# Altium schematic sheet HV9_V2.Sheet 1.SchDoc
size 431 x 279 mm
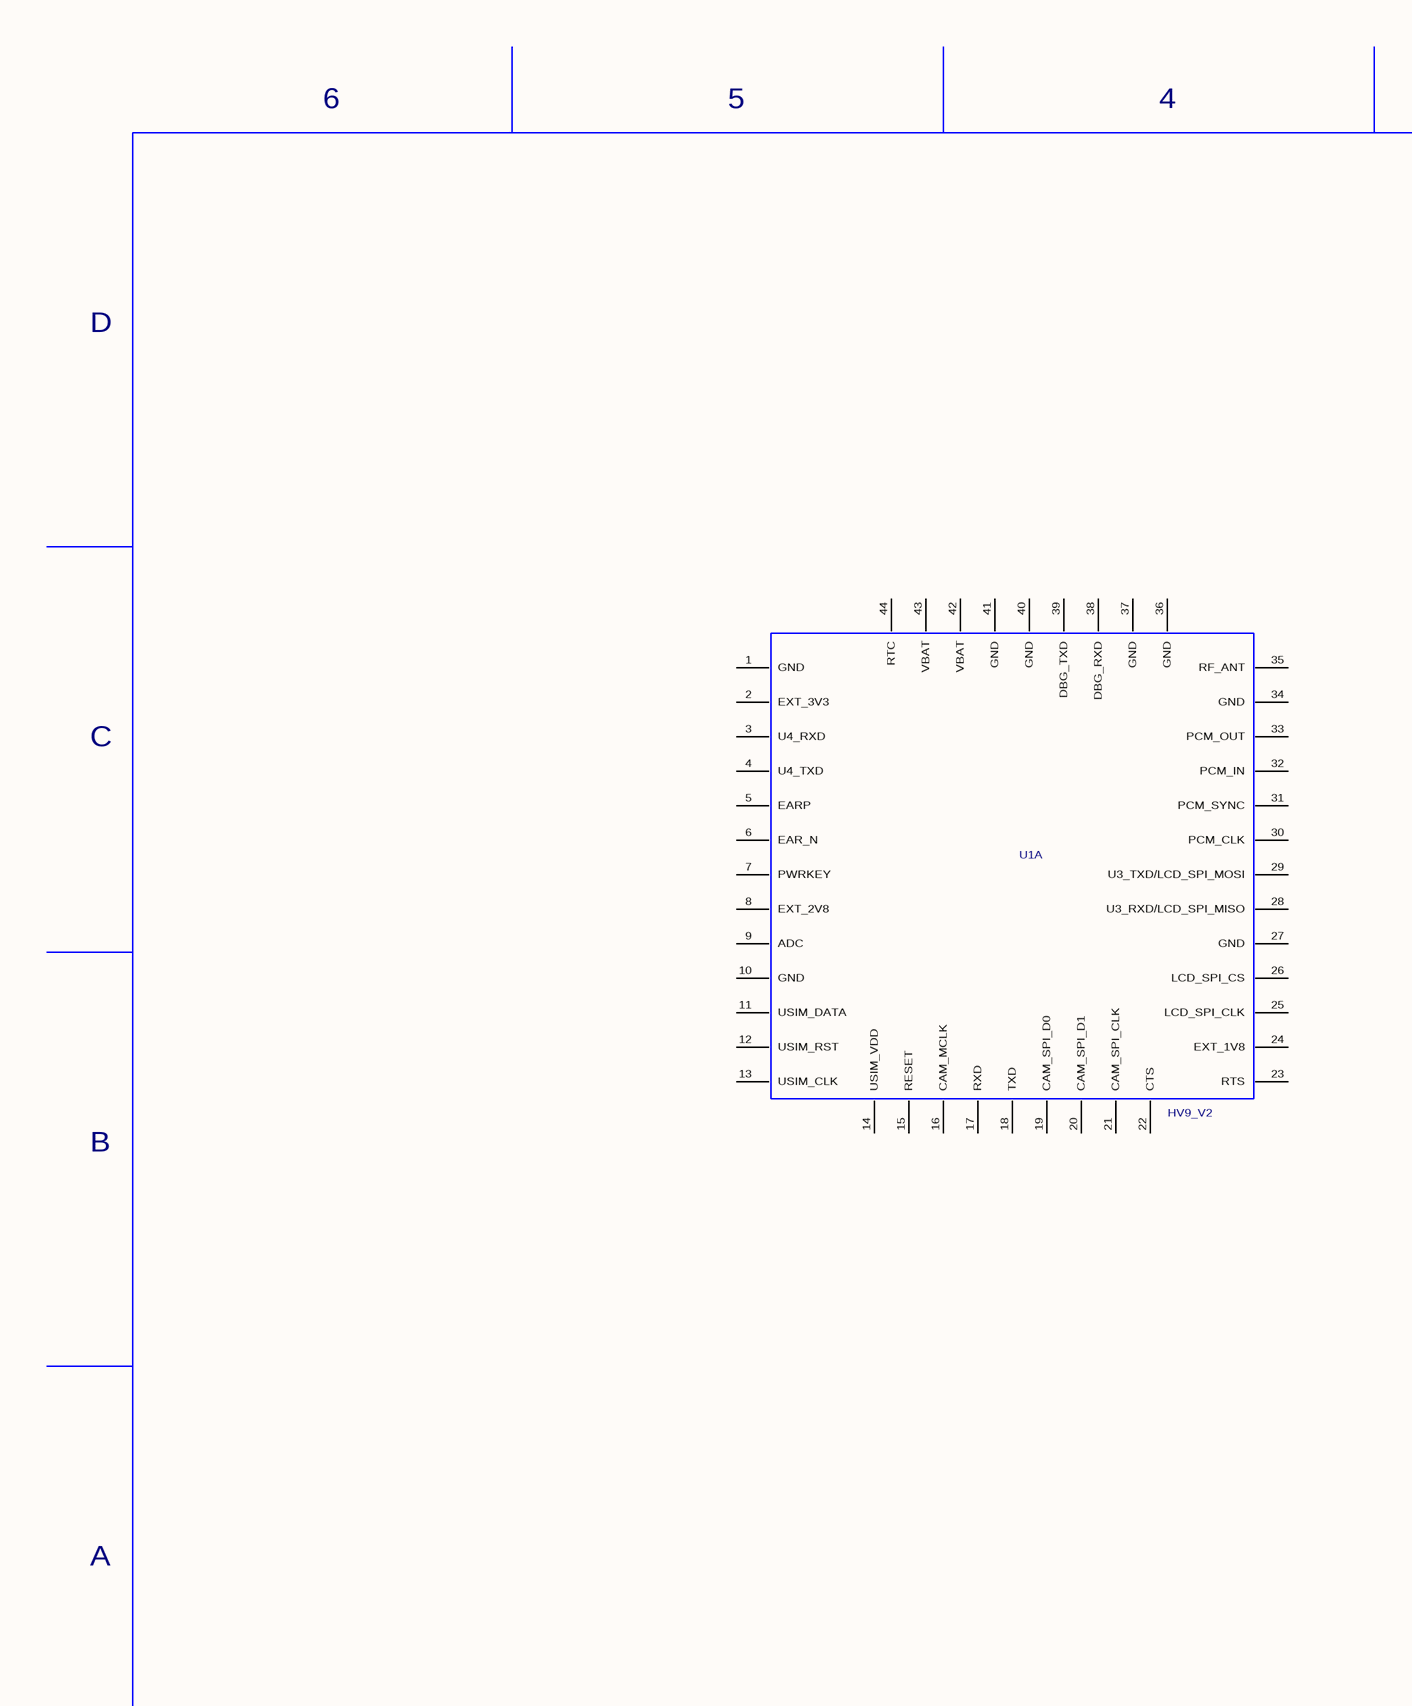
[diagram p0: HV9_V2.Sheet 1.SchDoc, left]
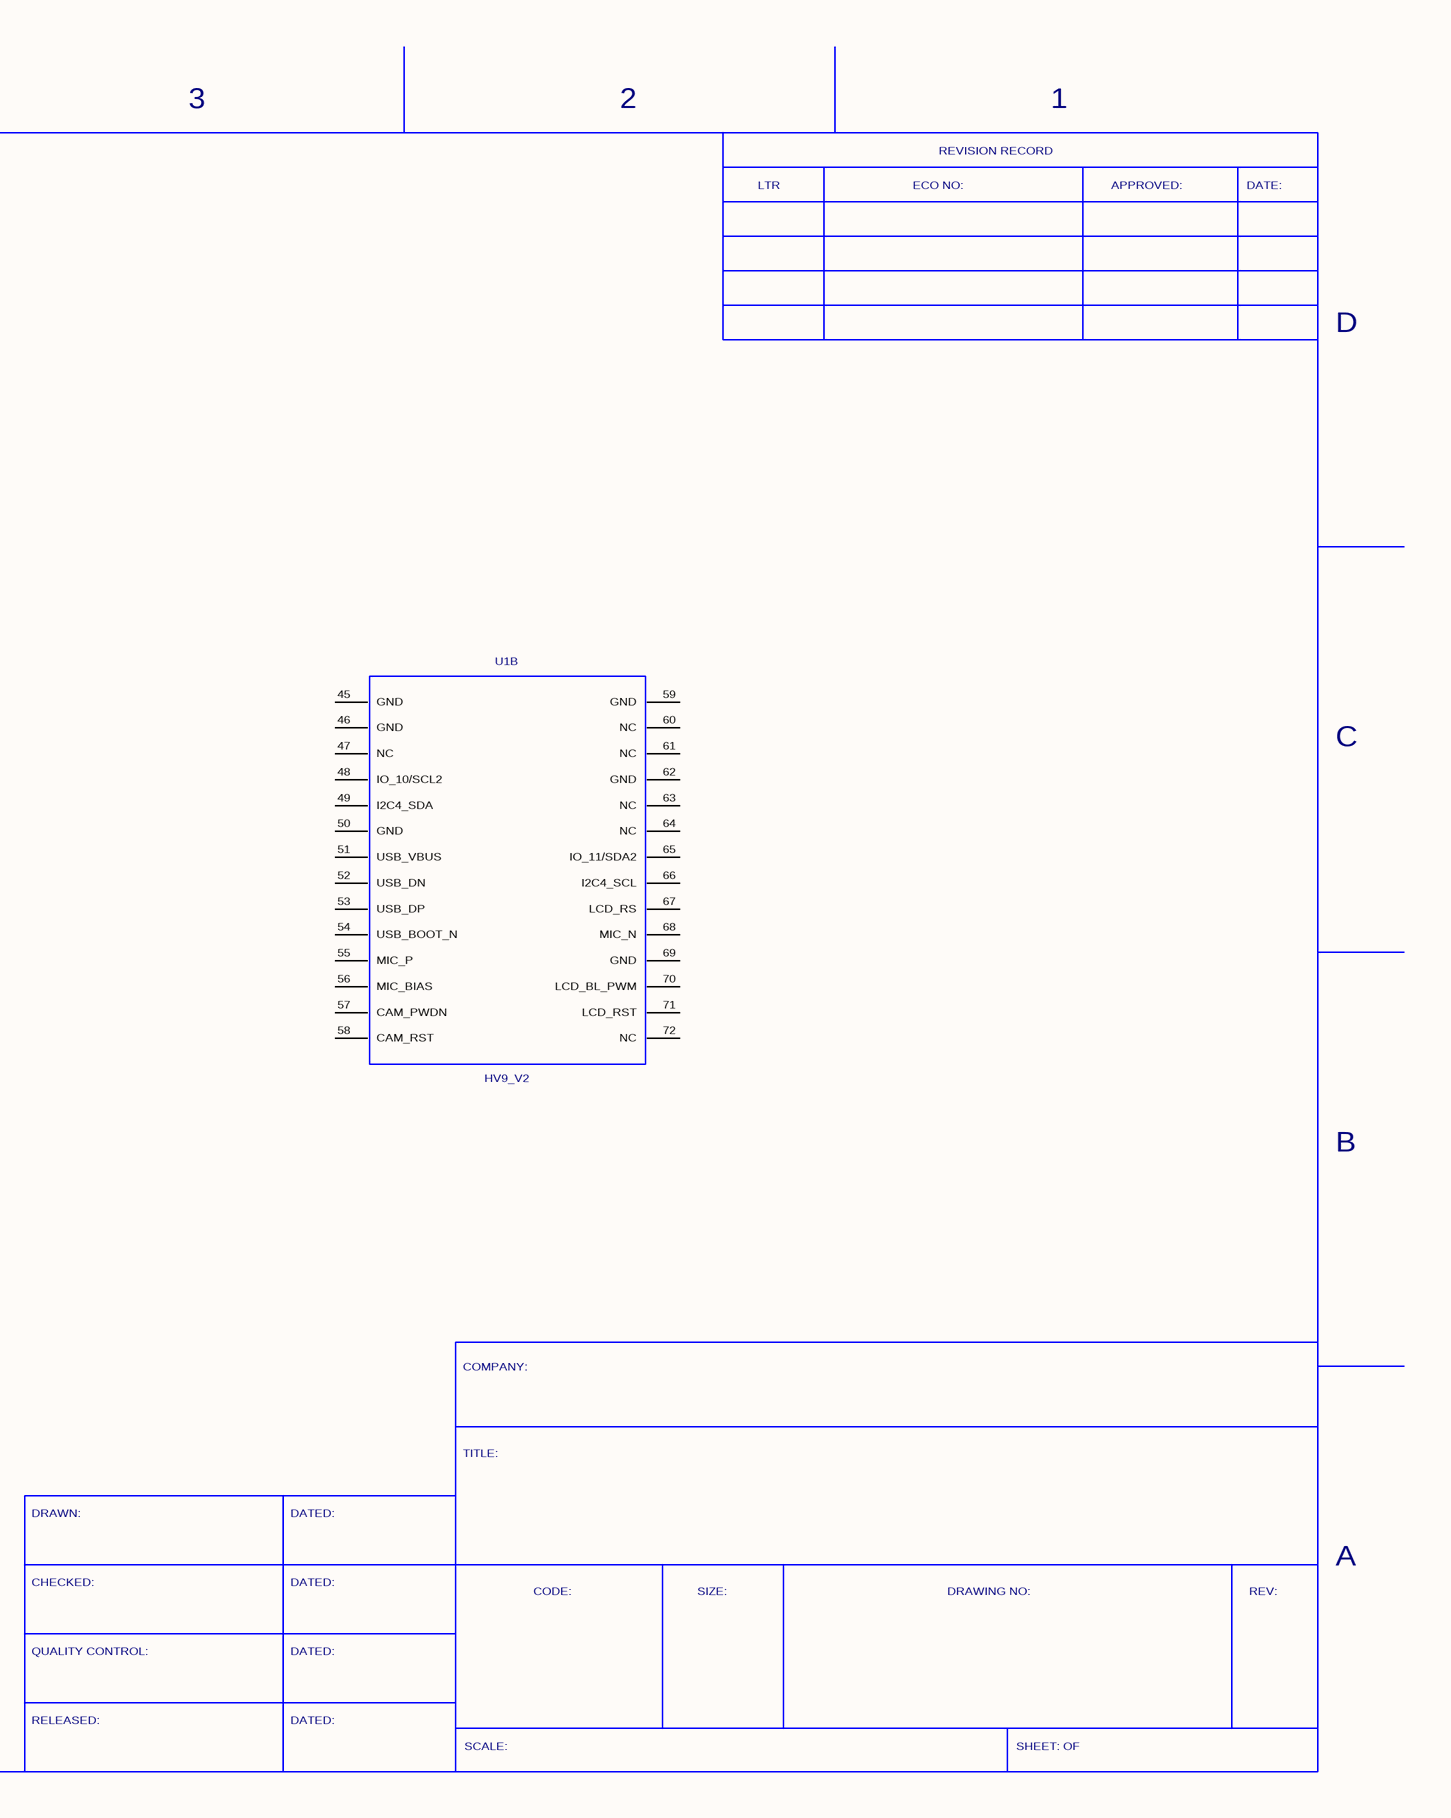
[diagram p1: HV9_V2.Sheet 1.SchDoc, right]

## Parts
U1  HV9_V2  [HV9_V2]  (parts A,B of 2)

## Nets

Not connected (* = marked no-connect by the designer): U1 1(GND) 2(EXT_3V3) 3(U4_RXD) 4(U4_TXD) 5(EARP) 6(EAR_N) 7(PWRKEY) 8(EXT_2V8) 9(ADC) 10(GND) 11(USIM_DATA) 12(USIM_RST) 13(USIM_CLK) 14(USIM_VDD) 15(RESET) 16(CAM_MCLK) 17(RXD) 18(TXD) 19(CAM_SPI_D0) 20(CAM_SPI_D1) 21(CAM_SPI_CLK) 22(CTS) 23(RTS) 24(EXT_1V8) 25(LCD_SPI_CLK) 26(LCD_SPI_CS) 27(GND) 28(U3_RXD/LCD_SPI_MISO) 29(U3_TXD/LCD_SPI_MOSI) 30(PCM_CLK) 31(PCM_SYNC) 32(PCM_IN) 33(PCM_OUT) 34(GND) 35(RF_ANT) 36(GND) 37(GND) 38(DBG_RXD) 39(DBG_TXD) 40(GND) 41(GND) 42(VBAT) 43(VBAT) 44(RTC) 45(GND) 46(GND) 47(NC) 48(IO_10/SCL2) 49(I2C4_SDA) 50(GND) 51(USB_VBUS) 52(USB_DN) 53(USB_DP) 54(USB_BOOT_N) 55(MIC_P) 56(MIC_BIAS) 57(CAM_PWDN) 58(CAM_RST) 59(GND) 60(NC) 61(NC) 62(GND) 63(NC) 64(NC) 65(IO_11/SDA2) 66(I2C4_SCL) 67(LCD_RS) 68(MIC_N) 69(GND) 70(LCD_BL_PWM) 71(LCD_RST) 72(NC)

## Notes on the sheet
- 6
- 5
- 4
- 3
- 2
- REVISION RECORD
- 1
- LTR
- ECO NO:
- APPROVED:
- DATE:
- D
- C
- B
- COMPANY:
- TITLE:
- DRAWN:
- DATED:
- A
- CHECKED:
- CODE:
- SIZE:
- DRAWING NO:
- REV:
- QUALITY CONTROL:
- RELEASED:
- SCALE:
- SHEET: OF

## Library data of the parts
U1 = HV9_V2: Geometry.Height: 2.4mm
